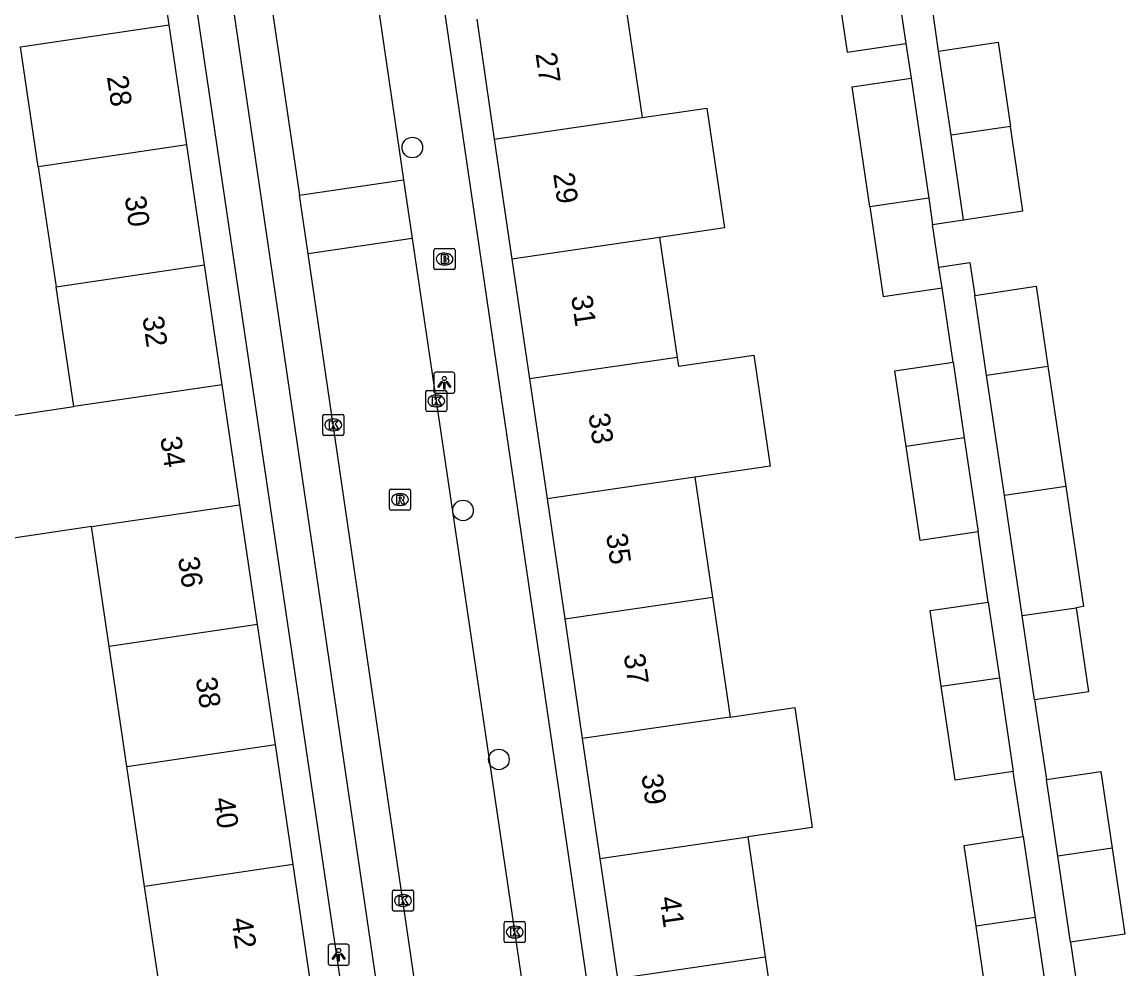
# Model space of a CAD drawing. Extents: x 159053 to 160041, y 380450 to 381422.
# Drawn here: x 159553.7 to 159606, y 381038.5 to 381083.5 of the extents above; entities that cross this region are included whole.
import ezdxf

# ---------------------------------------------------------------- set-up
doc = ezdxf.new("R2010")
doc.units = 0
for name, color, linetype in [('IMGEO_Boom', 7, 'Continuous'), ('IMGEO_Brandkraan', 7, 'Continuous'), ('IMGEO_Kolk', 7, 'Continuous'), ('IMGEO_Lichtpunt', 7, 'Continuous'), ('IMGEO_Pand', 7, 'Continuous'), ('IMGEO_Pand_nummerreeks', 7, 'Continuous'), ('IMGEO_Rijbaan_lokaal_open', 7, 'Continuous'), ('IMGEO_Rioolput', 7, 'Continuous'), ('IMGEO_Voetpad_op_trap', 7, 'Continuous'), ('IMGEO_Voetpad_open', 7, 'Continuous')]:
    doc.layers.add(name, color=color, linetype=linetype)

msp = doc.modelspace()

# ---------------------------------------------------------------- linework, layer by layer
at = {"layer": 'IMGEO_Boom'}
for centre in [(159572.223, 381077.531), (159574.627, 381060.305), (159576.328, 381048.487)]:
    msp.add_circle(centre, 0.489, dxfattribs=at)
at = {"layer": 'IMGEO_Brandkraan'}
for p, q in [((159573.324, 381072.738), (159574.176, 381072.738)), ((159573.249, 381071.812), (159573.249, 381072.664)), ((159573.737, 381072.518), (159573.762, 381072.518)), ((159574.25, 381072.664), (159574.25, 381071.812)), ((159574.176, 381071.738), (159573.324, 381071.738)), ((159573.76, 381071.958), (159573.735, 381071.958))]:
    msp.add_line(p, q, dxfattribs=at)
for points in [[(159573.324, 381072.738), (159574.176, 381072.738)], [(159573.249, 381071.812), (159573.249, 381072.664)], [(159573.597, 381072.438), (159573.597, 381072.038), (159573.81, 381072.038)], [(159573.828, 381072.438), (159573.597, 381072.438)], [(159573.776, 381072.357), (159573.722, 381072.357), (159573.722, 381072.281)], [(159573.722, 381072.281), (159573.775, 381072.281)], [(159573.784, 381072.205), (159573.722, 381072.205), (159573.722, 381072.124)], [(159574.25, 381072.664), (159574.25, 381071.812)], [(159574.176, 381071.738), (159573.324, 381071.738)], [(159573.722, 381072.124), (159573.784, 381072.124)]]:
    msp.add_lwpolyline(points, dxfattribs=at)
for centre, radius, start, end in [((159573.326, 381072.662), 0.0765, 91.552, 178.448), ((159573.326, 381072.662), 0.0765, 91.552, 178.448), ((159574.174, 381072.662), 0.0765, 1.552, 88.448), ((159574.174, 381072.662), 0.0765, 1.552, 88.448), ((159573.777, 381072.319), 0.0379, 267.8285, 90.9355), ((159573.785, 381072.164), 0.0404, 269.8759, 90.5077), ((159573.832, 381072.293), 0.145, 59.4692, 91.5367), ((159573.857, 381072.34), 0.0922, 285.5137, 58.1501), ((159573.862, 381072.148), 0.105, 301.3115, 78.989), ((159573.326, 381071.814), 0.0765, 181.552, 268.448), ((159573.326, 381071.814), 0.0765, 181.552, 268.448), ((159573.816, 381072.289), 0.251, 268.6676, 293.5347), ((159574.174, 381071.814), 0.0765, 271.552, 358.448), ((159574.174, 381071.814), 0.0765, 271.552, 358.448)]:
    msp.add_arc(centre, radius, start, end, dxfattribs=at)
for centre, major_axis, ratio, start_param, end_param in [((159573.736, 381072.238), (-0.387, 0.002), 0.722429, 4.712389, 7.853982), ((159573.761, 381072.238), (-0.39, 0.002), 0.717154, 1.570796, 4.712389)]:
    msp.add_ellipse(centre, major_axis=major_axis, ratio=ratio, start_param=start_param, end_param=end_param, dxfattribs=at)
at = {"layer": 'IMGEO_Kolk'}
for p, q in [((159572.855, 381065.075), (159572.855, 381065.927)), ((159572.93, 381066.001), (159573.782, 381066.001)), ((159573.856, 381065.927), (159573.856, 381065.075)), ((159573.343, 381065.781), (159573.368, 381065.781)), ((159568.044, 381064.866), (159568.896, 381064.866)), ((159573.782, 381065.001), (159572.93, 381065.001)), ((159573.366, 381065.221), (159573.341, 381065.221)), ((159567.969, 381063.94), (159567.969, 381064.792)), ((159568.457, 381064.646), (159568.482, 381064.646)), ((159568.97, 381064.792), (159568.97, 381063.94)), ((159568.896, 381063.866), (159568.044, 381063.866)), ((159568.48, 381064.086), (159568.455, 381064.086)), ((159571.278, 381041.364), (159571.278, 381042.216)), ((159571.353, 381042.29), (159572.205, 381042.29)), ((159571.766, 381042.07), (159571.791, 381042.07)), ((159572.279, 381042.216), (159572.279, 381041.364)), ((159572.205, 381041.29), (159571.353, 381041.29)), ((159571.789, 381041.51), (159571.764, 381041.51)), ((159576.654, 381040.795), (159577.506, 381040.795)), ((159576.579, 381039.869), (159576.579, 381040.721)), ((159577.067, 381040.575), (159577.092, 381040.575)), ((159577.58, 381040.721), (159577.58, 381039.869)), ((159577.506, 381039.795), (159576.654, 381039.795)), ((159577.09, 381040.015), (159577.065, 381040.015))]:
    msp.add_line(p, q, dxfattribs=at)
for points in [[(159572.855, 381065.075), (159572.855, 381065.927)], [(159572.93, 381066.001), (159573.782, 381066.001)], [(159573.856, 381065.927), (159573.856, 381065.075)], [(159573.176, 381065.701), (159573.299, 381065.701), (159573.299, 381065.55), (159573.429, 381065.701), (159573.593, 381065.701), (159573.447, 381065.55), (159573.6, 381065.301), (159573.448, 381065.301), (159573.363, 381065.465), (159573.299, 381065.398), (159573.299, 381065.301), (159573.176, 381065.301), (159573.176, 381065.701)], [(159568.044, 381064.866), (159568.896, 381064.866)], [(159573.782, 381065.001), (159572.93, 381065.001)], [(159567.969, 381063.94), (159567.969, 381064.792)], [(159568.29, 381064.566), (159568.413, 381064.566), (159568.413, 381064.415), (159568.543, 381064.566), (159568.707, 381064.566), (159568.561, 381064.415), (159568.714, 381064.166), (159568.562, 381064.166), (159568.477, 381064.33), (159568.413, 381064.263), (159568.413, 381064.166), (159568.29, 381064.166), (159568.29, 381064.566)], [(159568.97, 381064.792), (159568.97, 381063.94)], [(159568.896, 381063.866), (159568.044, 381063.866)], [(159571.278, 381041.364), (159571.278, 381042.216)], [(159571.353, 381042.29), (159572.205, 381042.29)], [(159571.599, 381041.99), (159571.722, 381041.99), (159571.722, 381041.839), (159571.852, 381041.99), (159572.016, 381041.99), (159571.87, 381041.839), (159572.023, 381041.59), (159571.871, 381041.59), (159571.786, 381041.754), (159571.722, 381041.687), (159571.722, 381041.59), (159571.599, 381041.59), (159571.599, 381041.99)], [(159572.279, 381042.216), (159572.279, 381041.364)], [(159572.205, 381041.29), (159571.353, 381041.29)], [(159576.654, 381040.795), (159577.506, 381040.795)], [(159576.579, 381039.869), (159576.579, 381040.721)], [(159576.9, 381040.495), (159577.023, 381040.495), (159577.023, 381040.344), (159577.153, 381040.495), (159577.317, 381040.495), (159577.171, 381040.344), (159577.324, 381040.095), (159577.172, 381040.095), (159577.087, 381040.259), (159577.023, 381040.192), (159577.023, 381040.095), (159576.9, 381040.095), (159576.9, 381040.495)], [(159577.58, 381040.721), (159577.58, 381039.869)], [(159577.506, 381039.795), (159576.654, 381039.795)]]:
    msp.add_lwpolyline(points, dxfattribs=at)
for centre, start, end in [((159572.932, 381065.925), 91.552, 178.448), ((159572.932, 381065.925), 91.552, 178.448), ((159573.78, 381065.925), 1.552, 88.448), ((159573.78, 381065.925), 1.552, 88.448), ((159568.046, 381064.79), 91.552, 178.448), ((159568.046, 381064.79), 91.552, 178.448), ((159568.894, 381064.79), 1.552, 88.448), ((159568.894, 381064.79), 1.552, 88.448), ((159572.932, 381065.077), 181.552, 268.448), ((159572.932, 381065.077), 181.552, 268.448), ((159573.78, 381065.077), 271.552, 358.448), ((159573.78, 381065.077), 271.552, 358.448), ((159568.046, 381063.942), 181.552, 268.448), ((159568.046, 381063.942), 181.552, 268.448), ((159568.894, 381063.942), 271.552, 358.448), ((159568.894, 381063.942), 271.552, 358.448), ((159571.355, 381042.214), 91.552, 178.448), ((159571.355, 381042.214), 91.552, 178.448), ((159572.203, 381042.214), 1.552, 88.448), ((159572.203, 381042.214), 1.552, 88.448), ((159571.355, 381041.366), 181.552, 268.448), ((159571.355, 381041.366), 181.552, 268.448), ((159572.203, 381041.366), 271.552, 358.448), ((159572.203, 381041.366), 271.552, 358.448), ((159576.656, 381040.719), 91.552, 178.448), ((159576.656, 381040.719), 91.552, 178.448), ((159577.504, 381040.719), 1.552, 88.448), ((159577.504, 381040.719), 1.552, 88.448), ((159576.656, 381039.871), 181.552, 268.448), ((159576.656, 381039.871), 181.552, 268.448), ((159577.504, 381039.871), 271.552, 358.448), ((159577.504, 381039.871), 271.552, 358.448)]:
    msp.add_arc(centre, 0.0765, start, end, dxfattribs=at)
for centre, major_axis, ratio, start_param, end_param in [((159573.342, 381065.501), (-0.387, 0.002), 0.722429, 4.712389, 7.853982), ((159573.367, 381065.501), (-0.39, 0.002), 0.717154, 1.570796, 4.712389), ((159568.456, 381064.366), (-0.387, 0.002), 0.722429, 4.712389, 7.853982), ((159568.481, 381064.366), (-0.39, 0.002), 0.717154, 1.570796, 4.712389), ((159571.765, 381041.79), (-0.387, 0.002), 0.722429, 4.712389, 7.853982), ((159571.79, 381041.79), (-0.39, 0.002), 0.717154, 1.570796, 4.712389), ((159577.066, 381040.295), (-0.387, 0.002), 0.722429, 4.712389, 7.853982), ((159577.091, 381040.295), (-0.39, 0.002), 0.717154, 1.570796, 4.712389)]:
    msp.add_ellipse(centre, major_axis=major_axis, ratio=ratio, start_param=start_param, end_param=end_param, dxfattribs=at)
at = {"layer": 'IMGEO_Lichtpunt'}
for p, q in [((159573.241, 381066.77), (159573.241, 381065.963)), ((159573.241, 381066.77), (159573.241, 381065.963)), ((159574.143, 381066.865), (159573.335, 381066.865)), ((159574.143, 381066.865), (159573.335, 381066.865)), ((159574.237, 381065.963), (159574.237, 381066.77)), ((159574.237, 381065.963), (159574.237, 381066.77)), ((159573.335, 381065.869), (159574.143, 381065.869)), ((159573.335, 381065.869), (159574.143, 381065.869)), ((159569.13, 381039.719), (159568.322, 381039.719)), ((159569.13, 381039.719), (159568.322, 381039.719)), ((159568.228, 381039.624), (159568.228, 381038.817)), ((159568.228, 381039.624), (159568.228, 381038.817)), ((159569.224, 381038.817), (159569.224, 381039.624)), ((159569.224, 381038.817), (159569.224, 381039.624)), ((159568.322, 381038.723), (159569.13, 381038.723)), ((159568.322, 381038.723), (159569.13, 381038.723))]:
    msp.add_line(p, q, dxfattribs=at)
for points in [[(159573.615, 381066.434), (159573.654, 381066.406), (159573.466, 381066.144), (159573.428, 381066.171), (159573.615, 381066.434)], [(159573.827, 381066.406), (159573.865, 381066.433), (159574.052, 381066.171), (159574.013, 381066.143), (159573.827, 381066.406)], [(159573.717, 381066.386), (159573.764, 381066.386), (159573.764, 381066.064), (159573.717, 381066.064), (159573.717, 381066.386)], [(159568.602, 381039.288), (159568.641, 381039.26), (159568.453, 381038.998), (159568.415, 381039.025), (159568.602, 381039.288)], [(159568.704, 381039.24), (159568.751, 381039.24), (159568.751, 381038.918), (159568.704, 381038.918), (159568.704, 381039.24)], [(159568.814, 381039.26), (159568.852, 381039.287), (159569.039, 381039.025), (159569, 381038.997), (159568.814, 381039.26)]]:
    msp.add_lwpolyline(points, dxfattribs=at)
for centre in [(159573.74, 381066.568), (159568.727, 381039.422)]:
    msp.add_circle(centre, 0.0994, dxfattribs=at)
for centre, start, end in [((159573.335, 381066.77), 90, 180), ((159573.335, 381066.77), 90, 180), ((159574.143, 381066.77), 0, 90), ((159574.143, 381066.77), 0, 90), ((159573.335, 381065.963), 180, 270), ((159573.335, 381065.963), 180, 270), ((159574.143, 381065.963), 270, 0), ((159574.143, 381065.963), 270, 360), ((159568.322, 381039.624), 90, 180), ((159568.322, 381039.624), 90, 180), ((159569.13, 381039.624), 0, 90), ((159569.13, 381039.624), 0, 90), ((159568.322, 381038.817), 180, 270), ((159568.322, 381038.817), 180, 270), ((159569.13, 381038.817), 270, 0), ((159569.13, 381038.817), 270, 360)]:
    msp.add_arc(centre, 0.0946, start, end, dxfattribs=at)
at = {"layer": 'IMGEO_Pand'}
for points in [[(159560.678, 381083.351), (159559.838, 381089.044)], [(159595.041, 381086.51), (159595.639, 381082.47)], [(159592.254, 381086.102), (159592.851, 381082.063), (159595.639, 381082.47)], [(159582.287, 381084.645), (159583.123, 381078.953)], [(159553.635, 381082.311), (159560.678, 381083.351)], [(159561.519, 381077.657), (159560.678, 381083.351)], [(159575.276, 381083.62), (159576.111, 381077.928)], [(159554.476, 381076.617), (159553.635, 381082.311)], [(159597.194, 381082.109), (159600.012, 381082.526), (159600.602, 381078.534)], [(159597.784, 381078.121), (159597.194, 381082.109)], [(159593.936, 381074.722), (159593.095, 381080.411), (159595.883, 381080.818)], [(159595.883, 381080.818), (159596.724, 381075.13)], [(159576.111, 381077.928), (159583.123, 381078.953)], [(159583.123, 381078.953), (159586.2, 381079.403), (159587.035, 381073.713), (159583.957, 381073.263)], [(159600.602, 381078.534), (159597.784, 381078.121)], [(159598.378, 381074.101), (159601.196, 381074.518), (159600.602, 381078.534)], [(159576.111, 381077.928), (159576.946, 381072.238)], [(159598.378, 381074.101), (159597.784, 381078.121)], [(159561.519, 381077.657), (159554.476, 381076.617)], [(159562.36, 381071.964), (159561.519, 381077.657)], [(159554.476, 381076.617), (159555.317, 381070.924)], [(159596.724, 381075.13), (159593.936, 381074.722)], [(159596.724, 381075.13), (159596.908, 381073.883)], [(159593.936, 381074.722), (159594.567, 381070.454), (159597.354, 381070.866)], [(159597.209, 381071.85), (159596.908, 381073.883)], [(159583.957, 381073.263), (159576.946, 381072.238)], [(159583.957, 381073.263), (159584.792, 381067.571)], [(159576.946, 381072.238), (159577.781, 381066.546)], [(159555.317, 381070.924), (159562.36, 381071.964)], [(159563.201, 381066.271), (159562.36, 381071.964)], [(159597.354, 381070.866), (159597.209, 381071.85)], [(159556.157, 381065.231), (159555.317, 381070.924)], [(159598.909, 381070.514), (159601.82, 381070.945), (159602.381, 381067.151)], [(159599.469, 381066.725), (159598.909, 381070.514)], [(159584.792, 381067.571), (159577.781, 381066.546)], [(159584.792, 381067.571), (159584.854, 381067.152), (159588.426, 381067.676), (159589.2, 381062.403), (159585.627, 381061.881)], [(159595.651, 381063.347), (159595.121, 381066.934), (159597.876, 381067.341)], [(159597.876, 381067.341), (159598.407, 381063.749)], [(159599.469, 381066.725), (159602.381, 381067.151)], [(159602.381, 381067.151), (159603.225, 381061.445)], [(159577.781, 381066.546), (159578.616, 381060.856)], [(159600.313, 381061.019), (159599.469, 381066.725)], [(159563.201, 381066.271), (159556.157, 381065.231)], [(159564.041, 381060.577), (159563.201, 381066.271)], [(159556.998, 381059.537), (159553.302, 381058.991), (159552.461, 381064.685), (159556.157, 381065.231)], [(159598.407, 381063.749), (159595.651, 381063.347)], [(159599.066, 381059.292), (159596.311, 381058.885), (159595.651, 381063.347)], [(159598.407, 381063.749), (159599.066, 381059.292)], [(159585.627, 381061.881), (159578.616, 381060.856)], [(159585.627, 381061.881), (159586.462, 381056.189)], [(159603.225, 381061.445), (159600.313, 381061.019)], [(159603.225, 381061.445), (159604.068, 381055.74), (159603.715, 381055.688)], [(159578.616, 381060.856), (159579.451, 381055.164)], [(159601.156, 381055.313), (159600.313, 381061.019)], [(159556.998, 381059.537), (159564.041, 381060.577)], [(159564.882, 381054.884), (159564.041, 381060.577)], [(159557.839, 381053.844), (159556.998, 381059.537)], [(159579.451, 381055.164), (159586.462, 381056.189)], [(159586.462, 381056.189), (159587.297, 381050.498)], [(159597.321, 381051.964), (159596.791, 381055.551), (159599.546, 381055.958)], [(159599.546, 381055.958), (159600.077, 381052.366)], [(159601.156, 381055.313), (159603.715, 381055.688)], [(159603.715, 381055.688), (159604.306, 381051.697), (159601.747, 381051.322)], [(159564.882, 381054.884), (159557.839, 381053.844)], [(159565.723, 381049.191), (159564.882, 381054.884)], [(159579.451, 381055.164), (159580.286, 381049.473)], [(159601.747, 381051.322), (159601.156, 381055.313)], [(159558.68, 381048.151), (159557.839, 381053.844)], [(159597.321, 381051.964), (159600.077, 381052.366)], [(159600.077, 381052.366), (159600.736, 381047.909)], [(159600.736, 381047.909), (159597.981, 381047.502), (159597.321, 381051.964)], [(159587.297, 381050.498), (159590.368, 381050.947), (159591.2, 381045.254), (159588.133, 381044.806)], [(159587.297, 381050.498), (159580.286, 381049.473)], [(159558.68, 381048.151), (159565.723, 381049.191)], [(159566.564, 381043.497), (159565.723, 381049.191)], [(159580.286, 381049.473), (159581.121, 381043.782)], [(159559.52, 381042.457), (159558.68, 381048.151)], [(159602.306, 381047.538), (159604.892, 381047.917), (159605.43, 381044.277)], [(159602.844, 381043.899), (159602.306, 381047.538)], [(159581.121, 381043.782), (159588.133, 381044.806)], [(159588.133, 381044.806), (159588.968, 381039.116)], [(159598.968, 381040.578), (159598.402, 381044.407), (159601.206, 381044.822)], [(159601.206, 381044.822), (159601.772, 381040.988)], [(159605.43, 381044.277), (159602.844, 381043.899)], [(159603.448, 381039.814), (159602.844, 381043.899)], [(159605.43, 381044.277), (159606.033, 381040.197), (159603.448, 381039.814)], [(159566.564, 381043.497), (159559.52, 381042.457)], [(159567.404, 381037.804), (159566.564, 381043.497)], [(159581.121, 381043.782), (159581.956, 381038.091)], [(159560.361, 381036.764), (159559.52, 381042.457)], [(159601.772, 381040.988), (159598.968, 381040.578)], [(159601.772, 381040.988), (159602.402, 381036.729)], [(159602.402, 381036.729), (159599.598, 381036.319), (159598.968, 381040.578)], [(159581.956, 381038.091), (159588.968, 381039.116)], [(159588.968, 381039.116), (159589.803, 381033.425)]]:
    msp.add_lwpolyline(points, dxfattribs=at)
at = {"layer": 'IMGEO_Rijbaan_lokaal_open'}
for points in [[(159560.701, 381117.152), (159566.872, 381075.271)], [(159565.779, 381116.931), (159567.081, 381108.31), (159571.387, 381078.814), (159571.803, 381076)], [(159566.872, 381075.271), (159571.803, 381076)], [(159571.803, 381076), (159572.215, 381073.211)], [(159567.281, 381072.482), (159566.872, 381075.271)], [(159572.215, 381073.211), (159567.281, 381072.482)], [(159572.215, 381073.211), (159577.073, 381040.334), (159582.77, 381001.343)], [(159577.803, 381000.616), (159567.281, 381072.482)]]:
    msp.add_lwpolyline(points, dxfattribs=at)
at = {"layer": 'IMGEO_Rioolput'}
for p, q in [((159571.135, 381060.394), (159571.135, 381061.246)), ((159571.21, 381061.32), (159572.062, 381061.32)), ((159572.136, 381061.246), (159572.136, 381060.394)), ((159571.623, 381061.1), (159571.648, 381061.1)), ((159572.062, 381060.32), (159571.21, 381060.32)), ((159571.646, 381060.54), (159571.621, 381060.54))]:
    msp.add_line(p, q, dxfattribs=at)
for points in [[(159571.135, 381060.394), (159571.135, 381061.246)], [(159571.21, 381061.32), (159572.062, 381061.32)], [(159572.136, 381061.246), (159572.136, 381060.394)], [(159571.724, 381061.018), (159571.472, 381061.02), (159571.472, 381060.62)], [(159571.472, 381060.62), (159571.596, 381060.62), (159571.596, 381060.782), (159571.607, 381060.782)], [(159571.65, 381060.939), (159571.596, 381060.939), (159571.596, 381060.858)], [(159571.596, 381060.858), (159571.648, 381060.858)], [(159571.654, 381060.753), (159571.725, 381060.62), (159571.865, 381060.62), (159571.8, 381060.746)], [(159572.062, 381060.32), (159571.21, 381060.32)]]:
    msp.add_lwpolyline(points, dxfattribs=at)
for centre, radius, start, end in [((159571.212, 381061.244), 0.0765, 91.552, 178.448), ((159571.212, 381061.244), 0.0765, 91.552, 178.448), ((159572.06, 381061.244), 0.0765, 1.552, 88.448), ((159572.06, 381061.244), 0.0765, 1.552, 88.448), ((159571.606, 381060.729), 0.0533, 26.0293, 88.6989), ((159571.632, 381061.047), 0.19, 274.7715, 282.9687), ((159571.656, 381060.843), 0.0964, 77.0061, 93.1865), ((159571.67, 381060.9), 0.0378, 276.6634, 79.6772), ((159571.723, 381060.908), 0.109, 350.3612, 89.416), ((159571.721, 381060.908), 0.112, 277.5842, 350.9817), ((159571.705, 381060.693), 0.108, 29.5134, 73.7905), ((159571.212, 381060.396), 0.0765, 181.552, 268.448), ((159571.212, 381060.396), 0.0765, 181.552, 268.448), ((159572.06, 381060.396), 0.0765, 271.552, 358.448), ((159572.06, 381060.396), 0.0765, 271.552, 358.448)]:
    msp.add_arc(centre, radius, start, end, dxfattribs=at)
for centre, major_axis, ratio, start_param, end_param in [((159571.622, 381060.82), (-0.387, 0.002), 0.722429, 4.712389, 7.853982), ((159571.647, 381060.82), (-0.39, 0.002), 0.717154, 1.570796, 4.712389)]:
    msp.add_ellipse(centre, major_axis=major_axis, ratio=ratio, start_param=start_param, end_param=end_param, dxfattribs=at)
at = {"layer": 'IMGEO_Voetpad_op_trap'}
for points in [[(159558.908, 381116.837), (159563.427, 381086.22), (159569.973, 381041.563), (159574.048, 381013.707), (159574.57, 381010.14), (159576.089, 381000), (159576.625, 380995.481), (159576.807, 380993.975)], [(159556.453, 381111.966), (159557.841, 381112.195), (159572.181, 381015.08), (159570.79, 381014.875)]]:
    msp.add_lwpolyline(points, dxfattribs=at)
at = {"layer": 'IMGEO_Voetpad_open'}
for points in [[(159585.319, 381015.173), (159583.892, 381014.966), (159567.971, 381123.474)], [(159597.194, 381082.109), (159596.756, 381085.155)], [(159595.639, 381082.47), (159595.883, 381080.818)], [(159596.908, 381073.883), (159598.378, 381074.101)], [(159597.209, 381071.85), (159598.679, 381072.067), (159598.909, 381070.514)], [(159597.876, 381067.341), (159597.354, 381070.866)], [(159599.546, 381055.958), (159599.066, 381059.292)], [(159601.747, 381051.322), (159602.306, 381047.538)], [(159601.206, 381044.822), (159600.736, 381047.909)], [(159603.448, 381039.814), (159603.927, 381036.575)]]:
    msp.add_lwpolyline(points, dxfattribs=at)

# ---------------------------------------------------------------- texts
at = {"layer": 'IMGEO_Pand_nummerreeks'}
for s, rotation, p in [('27', 278.3475, (159578.063, 381081.985)), ('28', 278.3999, (159557.727, 381080.89)), ('29', 278.3475, (159578.9, 381076.278)), ('30', 278.3999, (159558.57, 381075.178)), ('31', 278.3475, (159579.753, 381070.46)), ('32', 278.3999, (159559.412, 381069.473)), ('33', 278.3478, (159580.575, 381064.864)), ('34', 278.3994, (159560.256, 381063.759)), ('35', 278.3475, (159581.412, 381059.157)), ('36', 278.3999, (159561.099, 381058.048)), ('37', 278.3475, (159582.249, 381053.45)), ('38', 278.3999, (159561.943, 381052.333)), ('39', 278.3475, (159583.087, 381047.744)), ('40', 278.3999, (159562.787, 381046.622)), ('41', 278.3475, (159583.94, 381041.926)), ('42', 278.3999, (159563.629, 381040.917))]:
    msp.add_text(s, height=1, rotation=rotation, dxfattribs=at).set_placement(p)

doc.saveas('drawing.dxf')
